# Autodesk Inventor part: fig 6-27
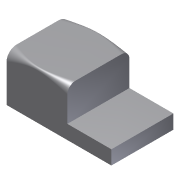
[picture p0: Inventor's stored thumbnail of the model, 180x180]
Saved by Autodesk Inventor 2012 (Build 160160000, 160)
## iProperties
Created: 2004-05
Part Number: fig 6-27
Document SubType Name: Modeling
Designer: CADCIM Technologies
Manufacturer: Standard
Standards Organization: Custom
Density: 1 g/cm^3
Material: Default
Author: CADCIM Technologies
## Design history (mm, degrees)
node "Sketch1"
sketch "Sketch2"
  geometry: L1 (0.098, 47.711)-(0.098, 0.049); L2 (0.098, 0.049)-(-105.483, 0.049); L3 (-105.483, 0.049)-(-105.483, 14.192); L4 (-105.483, 14.192)-(-61.139, 14.192); L5 (-61.139, 14.192)-(-61.139, 47.711); L6 (-61.139, 47.711)-(0.098, 47.711)
  constraints: 12 end point, 3 parallel, 2 perpendicular, 1 vertical
extrude "Extrusion1" new body sketch "Sketch2" stored distance "d0" = 62.5; taper "d1" = 0 deg
fillet "Fillet9" dims "d61" = 10, "d62" = 8, "d63" = 2, "d64" = 5
fillet "Fillet10" dims "d65" = 8, "d66" = 10, "d67" = 2, "d68" = 5
body "Solid1"
